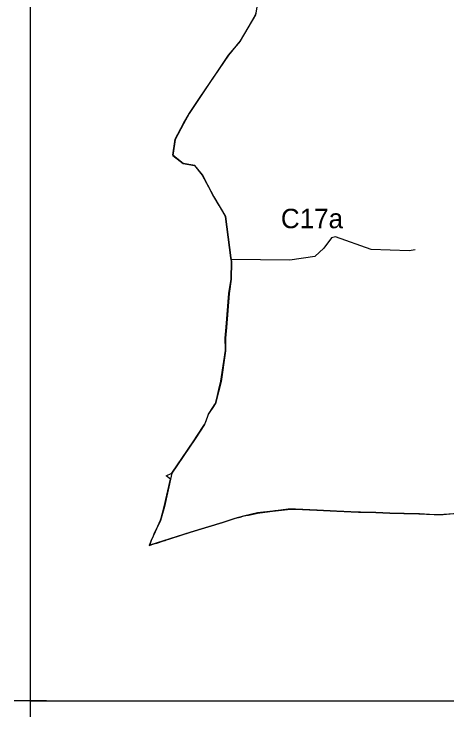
# Model space of a CAD drawing. Extents: x -478490 to -472450, y -1118050 to -1109550.
# Drawn here: x -478490 to -477155, y -1118050 to -1115880 of the extents above; entities that cross this region are included whole.
import ezdxf

# ---------------------------------------------------------------- set-up
doc = ezdxf.new("R2010")
doc.units = 0
for name, color, linetype in [('hranice kú', 7, 'Continuous'), ('Implicitní', 7, 'Continuous'), ('ObPÚ', 7, 'Continuous')]:
    doc.layers.add(name, color=color, linetype=linetype)

msp = doc.modelspace()

# ---------------------------------------------------------------- linework, layer by layer
at = {"layer": 'hranice kú'}
for p, q in [((-477745.7, -1115882.6), (-477792.7, -1115963.5)), ((-477743.9, -1115876.8), (-477745.7, -1115882.6)), ((-477792.7, -1115963.5), (-477829.2, -1116007.1)), ((-477829.2, -1116007.1), (-477917, -1116137.1)), ((-477917, -1116137.1), (-477949.4, -1116186.8)), ((-477949.4, -1116186.8), (-477967.8, -1116218.8)), ((-477967.8, -1116218.8), (-477992.9, -1116267.5)), ((-477992.9, -1116267.5), (-478000.3, -1116316.6)), ((-478000.3, -1116316.6), (-477968.7, -1116341.6)), ((-477968.7, -1116341.6), (-477933.8, -1116347.4)), ((-477933.8, -1116347.4), (-477910, -1116376.7)), ((-477910, -1116376.7), (-477876.7, -1116438.2)), ((-477876.7, -1116438.2), (-477873.6, -1116444)), ((-477873.6, -1116444), (-477837.5, -1116504.5)), ((-477837.5, -1116504.5), (-477821.5, -1116632.6)), ((-477821.5, -1116632.6), (-477819.1, -1116643.3)), ((-477819.1, -1116643.3), (-477819.9, -1116698.8)), ((-477819.9, -1116698.8), (-477826.9, -1116742.9)), ((-477826.9, -1116742.9), (-477835, -1116847.4)), ((-477835, -1116847.4), (-477838.2, -1116880.3)), ((-477838.2, -1116880.3), (-477837.4, -1116919.6)), ((-477837.4, -1116919.6), (-477851.4, -1117014.1)), ((-477851.4, -1117014.1), (-477868.8, -1117081.8)), ((-477871.9, -1117086.5), (-477874.9, -1117091.3)), ((-477868.8, -1117081.8), (-477871.9, -1117086.5)), ((-477874.9, -1117091.3), (-477889.7, -1117114.6)), ((-477889.7, -1117114.6), (-477902.7, -1117146.6)), ((-477902.7, -1117146.6), (-477931, -1117190.8)), ((-477931, -1117190.8), (-478003, -1117297.4)), ((-478003, -1117297.4), (-478026.4, -1117400.7)), ((-478026.4, -1117400.7), (-478038.6, -1117443)), ((-477683, -1117413.2), (-477646.5, -1117409)), ((-477646.5, -1117409), (-477622.5, -1117408.8)), ((-477622.5, -1117408.8), (-477556, -1117411.8)), ((-477556, -1117411.8), (-477494.1, -1117414.8)), ((-477802.8, -1117435.4), (-477797.7, -1117434)), ((-477797.7, -1117434), (-477792.8, -1117432.8)), ((-477792.8, -1117432.8), (-477783.8, -1117430)), ((-477783.8, -1117430), (-477771.4, -1117427.5)), ((-477771.4, -1117427.5), (-477766.4, -1117426.5)), ((-477766.4, -1117426.5), (-477761.5, -1117425.5)), ((-477761.5, -1117425.5), (-477739.4, -1117421.1)), ((-477739.4, -1117421.1), (-477692.8, -1117414.3)), ((-477692.8, -1117414.3), (-477683, -1117413.2)), ((-477494.1, -1117414.8), (-477427.6, -1117417.5)), ((-477427.6, -1117417.5), (-477374.1, -1117418.9)), ((-477374.1, -1117418.9), (-477330.4, -1117420.6)), ((-477330.4, -1117420.6), (-477287.5, -1117422.1)), ((-477287.5, -1117422.1), (-477240.8, -1117423)), ((-477240.8, -1117423), (-477193.8, -1117425.2)), ((-477193.8, -1117425.2), (-477165.8, -1117424.6)), ((-477165.8, -1117424.6), (-477134.7, -1117422.1)), ((-478038.6, -1117443), (-478058.5, -1117486)), ((-477945.6, -1117479.7), (-477846.5, -1117449.7)), ((-477846.5, -1117449.7), (-477810.1, -1117437.4)), ((-477810.1, -1117437.4), (-477802.8, -1117435.4)), ((-478062.4, -1117495), (-478065.9, -1117501.8)), ((-478058.5, -1117486), (-478062.4, -1117495)), ((-478009.3, -1117500.1), (-477945.6, -1117479.7)), ((-478065.9, -1117501.8), (-478072.8, -1117520.4)), ((-478072.8, -1117520.4), (-478058.8, -1117515.9)), ((-478058.8, -1117515.9), (-478054.3, -1117514.5)), ((-478054.3, -1117514.5), (-478049.8, -1117513.1)), ((-478049.8, -1117513.1), (-478028.9, -1117506.3)), ((-478028.9, -1117506.3), (-478024.4, -1117504.9)), ((-478024.4, -1117504.9), (-478019.9, -1117503.5)), ((-478019.9, -1117503.5), (-478009.3, -1117500.1))]:
    msp.add_line(p, q, dxfattribs=at)
at = {"layer": 'Implicitní'}
for p, q in [((-478440.1, -1117950.1), (-478440.1, -1118050.1)), ((-478390.1, -1118000.1), (-478490.1, -1118000.1))]:
    msp.add_line(p, q, dxfattribs=at)
msp.add_lwpolyline([(-478440.1, -1118000.1), (-472500.1, -1118000.1), (-472500.1, -1109600.1), (-478440.1, -1109600.1)], close=True, dxfattribs=at)
msp.add_lwpolyline([(-477252.1, -1116607.9), (-477271, -1116610.6), (-477388.8, -1116606.9), (-477498.3, -1116567.2), (-477510.5, -1116570.9), (-477534.4, -1116602.8), (-477562.2, -1116628.8), (-477639.7, -1116640.1), (-477820.3, -1116637.9)], dxfattribs=at)
at = {"layer": 'ObPÚ'}
for points in [[(-477835.4, -1116846.6), (-477827.3, -1116742.4), (-477820, -1116698.1), (-477819.2, -1116642.7), (-477821.6, -1116632.3), (-477838, -1116504.3), (-477857.1, -1116470.7), (-477873.5, -1116443), (-477876.4, -1116437.5), (-477908.6, -1116376.5), (-477932.5, -1116347.3), (-477968.1, -1116341.6), (-477983.2, -1116329.6), (-478000.1, -1116315.6), (-477992.6, -1116266.4), (-477967.7, -1116217.9), (-477949, -1116186), (-477916, -1116136), (-477827.8, -1116006.6), (-477791.1, -1115962.3), (-477744.4, -1115881.6), (-477737.4, -1115839.5)], [(-477133.3, -1117422.8), (-477164, -1117425.1), (-477192.4, -1117425.6), (-477239.2, -1117423.4), (-477286.2, -1117422.1), (-477330.8, -1117420.4), (-477373.9, -1117418.6), (-477420.9, -1117417.5), (-477422.1, -1117417.6), (-477424.2, -1117417.6), (-477428.8, -1117417.3), (-477494.8, -1117414.2), (-477554.5, -1117411.8), (-477621.5, -1117408.7), (-477644.7, -1117408.3), (-477682.1, -1117413.5), (-477685.9, -1117414), (-477688.8, -1117414.4), (-477691.7, -1117414.8), (-477738.6, -1117419.4), (-477782.5, -1117430.5), (-477809, -1117437.3), (-477845.5, -1117449.8), (-477945.1, -1117479.5), (-478009.4, -1117499.8), (-478071.7, -1117519.9), (-478064.8, -1117501.6), (-478057.7, -1117486.3), (-478038.7, -1117442.8), (-478036.7, -1117435.8), (-478026.6, -1117400.8), (-478007.7, -1117316.1), (-478020.6, -1117306), (-478003, -1117297.8), (-478003, -1117297.8), (-477955, -1117226.7), (-477932.9, -1117194), (-477930.9, -1117191), (-477927.8, -1117186.2), (-477902.4, -1117146.7), (-477898.9, -1117138.5), (-477889.8, -1117115.2), (-477874.4, -1117091.1), (-477871.5, -1117086.6), (-477868.9, -1117082), (-477862.7, -1117057.3), (-477855.8, -1117029.9), (-477851.7, -1117013.6), (-477838.1, -1116918.8), (-477838.2, -1116915), (-477838.5, -1116880.1), (-477835.4, -1116846.6)]]:
    msp.add_lwpolyline(points, dxfattribs=at)

# ---------------------------------------------------------------- texts
at = {"layer": 'Implicitní'}
msp.add_text('C17a', height=60, dxfattribs=at).set_placement((-477666.8, -1116541))

doc.saveas('drawing.dxf')
